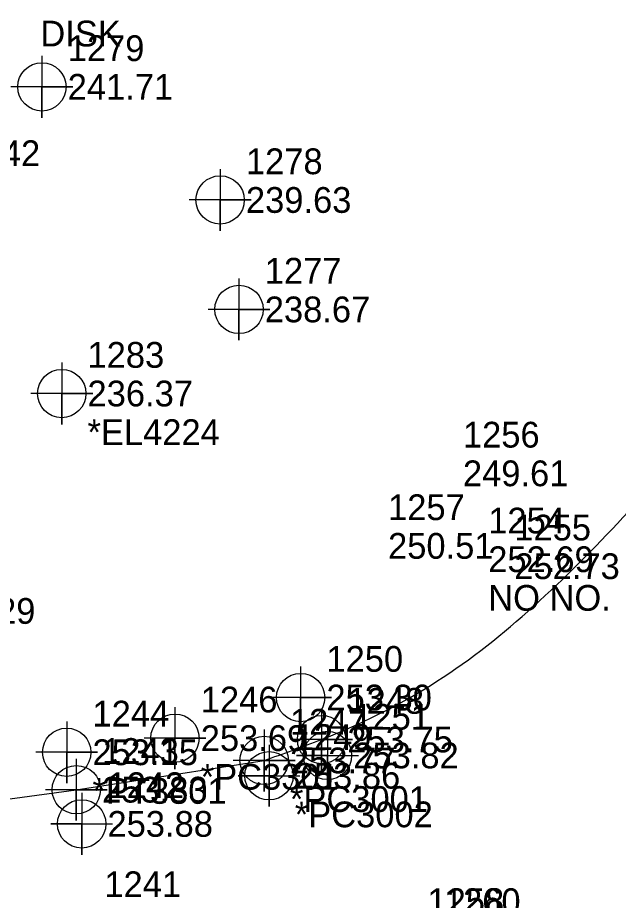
# Model space of a CAD drawing. Extents: x 2130621 to 2131998, y 642516 to 644503.
# Drawn here: x 2131142.4 to 2131200.6, y 643203.1 to 643288.8 of the extents above; entities that cross this region are included whole.
import ezdxf

# ---------------------------------------------------------------- set-up
doc = ezdxf.new("R2010")
doc.units = 0
for name, color, linetype in [('Exist Guardrail Cogo Comment', 7, 'Continuous'), ('Exist Guardrail Cogo Elevation', 7, 'Continuous'), ('Exist Guardrail Cogo Number', 7, 'Continuous'), ('Exist Guardrail Cogo Point CELL', 7, 'Continuous'), ('Exist Other Culture Anchor (Guy Wire) Cogo Elevation', 7, 'Continuous'), ('Exist Other Culture Anchor (Guy Wire) Cogo Number', 7, 'Continuous'), ('Exist Other Culture Fence Line Cogo Elevation', 7, 'Continuous'), ('Exist Right of Way Monument Cogo Comment', 7, 'Continuous'), ('Exist Roads EOP', 7, 'Continuous'), ('Exist Roads EOP Cogo Comment', 7, 'Continuous'), ('Exist Roads EOP Cogo Elevation', 7, 'Continuous'), ('Exist Roads EOP Cogo Number', 7, 'Continuous'), ('Exist Roads EOP Cogo Point CELL', 7, 'Continuous'), ('Exist Roads EOT Cogo Comment', 7, 'Continuous'), ('Exist Roads EOT Cogo Elevation', 7, 'Continuous'), ('Exist Roads EOT Cogo Number', 7, 'Continuous'), ('Exist Roads EOT Cogo Point CELL', 7, 'Continuous'), ('Exist Structure Minor Pipes RCP 24 Inch Cogo Comment', 7, 'Continuous'), ('Exist Structure Minor Pipes RCP 24 Inch Cogo Elevation', 7, 'Continuous'), ('Exist Structure Minor Pipes RCP 24 Inch Cogo Number', 7, 'Continuous'), ('Exist Structure Minor Pipes RCP 24 Inch Cogo Point CELL', 7, 'Continuous'), ('Exist Utilities Other Traffic Signal Box Cogo Elevation', 7, 'Continuous'), ('Exist Utilities Other Traffic Signal Box Cogo Number', 7, 'Continuous'), ('Exist Utilities Power Joint Use Telephone Cogo Comment', 7, 'Continuous'), ('Exist Utilities Power Joint Use Telephone Cogo Elevation', 7, 'Continuous'), ('Exist Utilities Power Joint Use Telephone Cogo Number', 7, 'Continuous'), ('Exist Vegetation Woods Line Cogo Elevation', 7, 'Continuous'), ('Exist Vegetation Woods Line Cogo Number', 7, 'Continuous'), ('Exist Vegetation Woods Line Cogo Point CELL', 7, 'Continuous')]:
    doc.layers.add(name, color=color, linetype=linetype)

msp = doc.modelspace()

# ---------------------------------------------------------------- linework, layer by layer
at = {"layer": 'Exist Guardrail Cogo Point CELL'}
for points in [[(2131169.785, 643225.794), (2131169.785, 643219.794), (2131169.785, 643222.794), (2131172.785, 643222.794), (2131166.785, 643222.794)], [(2131157.601, 643221.854), (2131157.601, 643215.854), (2131157.601, 643218.854), (2131160.601, 643218.854), (2131154.601, 643218.854)], [(2131147.104, 643220.485), (2131147.104, 643214.485), (2131147.104, 643217.485), (2131150.104, 643217.485), (2131144.104, 643217.485)]]:
    msp.add_lwpolyline(points, dxfattribs=at)
for centre in [(2131169.785, 643222.794), (2131157.601, 643218.854), (2131147.104, 643217.485)]:
    msp.add_circle(centre, 2.344, dxfattribs=at)
at = {"layer": 'Exist Roads EOP'}
msp.add_lwpolyline([(2131123.476, 643210.518), (2131148.036, 643213.856), (2131166.249, 643216.695)], dxfattribs=at)
msp.add_spline([(2131166.249, 643216.695), (2131171.813, 643218.724), (2131182.371, 643223.973), (2131191.812, 643231.149), (2131200.501, 643239.699), (2131208.807, 643249.07), (2131216.067, 643259.003), (2131218.719, 643264.347), (2131220.536, 643270.096), (2131222.844, 643282.008), (2131224.358, 643293.924), (2131224.876, 643317.79), (2131222.063, 643367.672), (2131218.545, 643416.811), (2131214.319, 643466.346), (2131209.174, 643515.667), (2131202.794, 643565.155), (2131195.047, 643613.994), (2131186.401, 643662.476), (2131176.011, 643711.405), (2131164.615, 643759.89), (2131151.874, 643807.853), (2131137.855, 643855.407), (2131122.573, 643902.857), (2131105.962, 643949.486), (2131091.535, 643988.044)], degree=3, dxfattribs=at)
at = {"layer": 'Exist Roads EOP Cogo Point CELL'}
for points in [[(2131171.813, 643221.724), (2131171.813, 643215.724), (2131171.813, 643218.724), (2131174.813, 643218.724), (2131168.813, 643218.724)], [(2131166.249, 643219.695), (2131166.249, 643213.695), (2131166.249, 643216.695), (2131169.249, 643216.695), (2131163.249, 643216.695)], [(2131148.036, 643216.856), (2131148.036, 643210.856), (2131148.036, 643213.856), (2131151.036, 643213.856), (2131145.036, 643213.856)]]:
    msp.add_lwpolyline(points, dxfattribs=at)
for centre in [(2131171.813, 643218.724), (2131166.249, 643216.695), (2131148.036, 643213.856)]:
    msp.add_circle(centre, 2.344, dxfattribs=at)
at = {"layer": 'Exist Roads EOT Cogo Point CELL'}
for points in [[(2131172.387, 643220.18), (2131172.387, 643214.18), (2131172.387, 643217.18), (2131169.387, 643217.18), (2131175.387, 643217.18)], [(2131166.718, 643218.208), (2131166.718, 643212.208), (2131166.718, 643215.208), (2131163.718, 643215.208), (2131169.718, 643215.208)], [(2131148.557, 643213.535), (2131148.557, 643207.535), (2131148.557, 643210.535), (2131145.557, 643210.535), (2131151.557, 643210.535)]]:
    msp.add_lwpolyline(points, dxfattribs=at)
for centre in [(2131172.387, 643217.18), (2131166.718, 643215.208), (2131148.557, 643210.535)]:
    msp.add_circle(centre, 2.344, dxfattribs=at)
at = {"layer": 'Exist Structure Minor Pipes RCP 24 Inch Cogo Point CELL'}
msp.add_lwpolyline([(2131146.622, 643255.296), (2131146.622, 643249.296), (2131146.622, 643252.296), (2131149.622, 643252.296), (2131143.622, 643252.296)], dxfattribs=at)
msp.add_circle((2131146.622, 643252.296), 2.344, dxfattribs=at)
at = {"layer": 'Exist Vegetation Woods Line Cogo Point CELL'}
for points in [[(2131144.7, 643285.051), (2131144.7, 643279.051), (2131144.7, 643282.051), (2131147.7, 643282.051), (2131141.7, 643282.051)], [(2131161.98, 643274.077), (2131161.98, 643268.077), (2131161.98, 643271.077), (2131164.98, 643271.077), (2131158.98, 643271.077)], [(2131163.809, 643263.457), (2131163.809, 643257.457), (2131163.809, 643260.457), (2131166.809, 643260.457), (2131160.809, 643260.457)]]:
    msp.add_lwpolyline(points, dxfattribs=at)
for centre in [(2131144.7, 643282.051), (2131161.98, 643271.077), (2131163.809, 643260.457)]:
    msp.add_circle(centre, 2.344, dxfattribs=at)

# ---------------------------------------------------------------- texts
at = {"layer": 'Exist Guardrail Cogo Comment'}
for s, p in [('*PC3301', (2131160.101, 643213.854)), ('*PT3301', (2131149.604, 643212.485))]:
    msp.add_text(s, height=2.5, dxfattribs=at).set_placement(p)
at = {"layer": 'Exist Guardrail Cogo Elevation'}
for s, p in [('253.30', (2131172.285, 643221.544)), ('253.69', (2131160.101, 643217.604)), ('253.15', (2131149.604, 643216.235))]:
    msp.add_text(s, height=2.5, dxfattribs=at).set_placement(p)
at = {"layer": 'Exist Guardrail Cogo Number'}
for s, p in [('1250', (2131172.285, 643225.294)), ('1246', (2131160.101, 643221.354)), ('1244', (2131149.604, 643219.985))]:
    msp.add_text(s, height=2.5, dxfattribs=at).set_placement(p)
at = {"layer": 'Exist Other Culture Anchor (Guy Wire) Cogo Elevation'}
for s, p in [('249.61', (2131185.519, 643243.301)), ('250.51', (2131178.26, 643236.262))]:
    msp.add_text(s, height=2.5, dxfattribs=at).set_placement(p)
at = {"layer": 'Exist Other Culture Anchor (Guy Wire) Cogo Number'}
for s, p in [('1256', (2131185.519, 643247.051)), ('1257', (2131178.26, 643240.012))]:
    msp.add_text(s, height=2.5, dxfattribs=at).set_placement(p)
at = {"layer": 'Exist Other Culture Fence Line Cogo Elevation'}
msp.add_text('244.42', height=2.5, dxfattribs=at).set_placement((2131134.309, 643274.359))
at = {"layer": 'Exist Right of Way Monument Cogo Comment'}
msp.add_text('DISK', height=2.5, dxfattribs=at).set_placement((2131144.551, 643285.975))
at = {"layer": 'Exist Roads EOP Cogo Comment'}
msp.add_text('*PC3001', height=2.5, dxfattribs=at).set_placement((2131168.749, 643211.695))
at = {"layer": 'Exist Roads EOP Cogo Elevation'}
for s, p in [('253.75', (2131174.313, 643217.474)), ('253.77', (2131168.749, 643215.445)), ('253.83', (2131150.536, 643212.606))]:
    msp.add_text(s, height=2.5, dxfattribs=at).set_placement(p)
at = {"layer": 'Exist Roads EOP Cogo Number'}
for s, p in [('1248', (2131174.313, 643221.224)), ('1247', (2131168.749, 643219.195)), ('1243', (2131150.536, 643216.356))]:
    msp.add_text(s, height=2.5, dxfattribs=at).set_placement(p)
at = {"layer": 'Exist Roads EOT Cogo Comment'}
msp.add_text('*PC3002', height=2.5, dxfattribs=at).set_placement((2131169.218, 643210.208))
at = {"layer": 'Exist Roads EOT Cogo Elevation'}
for s, p in [('253.82', (2131174.887, 643215.93)), ('253.86', (2131169.218, 643213.958)), ('253.88', (2131151.057, 643209.285))]:
    msp.add_text(s, height=2.5, dxfattribs=at).set_placement(p)
at = {"layer": 'Exist Roads EOT Cogo Number'}
for s, p in [('1251', (2131174.887, 643219.68)), ('1249', (2131169.218, 643217.708)), ('1242', (2131151.057, 643213.035)), ('1241', (2131150.756, 643203.429)), ('1258', (2131182.081, 643201.791)), ('1260', (2131183.674, 643201.783))]:
    msp.add_text(s, height=2.5, dxfattribs=at).set_placement(p)
at = {"layer": 'Exist Structure Minor Pipes RCP 24 Inch Cogo Comment'}
msp.add_text('*EL4224', height=2.5, dxfattribs=at).set_placement((2131149.122, 643247.296))
at = {"layer": 'Exist Structure Minor Pipes RCP 24 Inch Cogo Elevation'}
msp.add_text('236.37', height=2.5, dxfattribs=at).set_placement((2131149.122, 643251.046))
at = {"layer": 'Exist Structure Minor Pipes RCP 24 Inch Cogo Number'}
msp.add_text('1283', height=2.5, dxfattribs=at).set_placement((2131149.122, 643254.796))
at = {"layer": 'Exist Utilities Other Traffic Signal Box Cogo Elevation'}
msp.add_text('252.73', height=2.5, dxfattribs=at).set_placement((2131190.501, 643234.289))
at = {"layer": 'Exist Utilities Other Traffic Signal Box Cogo Number'}
msp.add_text('1255', height=2.5, dxfattribs=at).set_placement((2131190.501, 643238.039))
at = {"layer": 'Exist Utilities Power Joint Use Telephone Cogo Comment'}
msp.add_text('NO NO.', height=2.5, dxfattribs=at).set_placement((2131187.971, 643231.217))
at = {"layer": 'Exist Utilities Power Joint Use Telephone Cogo Elevation'}
msp.add_text('252.69', height=2.5, dxfattribs=at).set_placement((2131187.971, 643234.967))
at = {"layer": 'Exist Utilities Power Joint Use Telephone Cogo Number'}
msp.add_text('1254', height=2.5, dxfattribs=at).set_placement((2131187.971, 643238.717))
at = {"layer": 'Exist Vegetation Woods Line Cogo Elevation'}
for s, p in [('241.71', (2131147.2, 643280.801)), ('239.63', (2131164.48, 643269.827)), ('238.67', (2131166.309, 643259.207)), ('247.29', (2131133.846, 643229.95))]:
    msp.add_text(s, height=2.5, dxfattribs=at).set_placement(p)
at = {"layer": 'Exist Vegetation Woods Line Cogo Number'}
for s, p in [('1279', (2131147.2, 643284.551)), ('1278', (2131164.48, 643273.577)), ('1277', (2131166.309, 643262.957))]:
    msp.add_text(s, height=2.5, dxfattribs=at).set_placement(p)

doc.saveas('drawing.dxf')
